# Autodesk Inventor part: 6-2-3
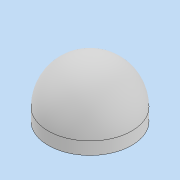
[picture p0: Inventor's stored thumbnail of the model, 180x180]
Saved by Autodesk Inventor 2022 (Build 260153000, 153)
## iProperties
Created: 2021-07
Part Number: 6-2-3
Material: 一般
Document SubType Name: Modeling
Designer: DesignLab
Density: 1 g/cm^3
Appearance: 既定
Author: DesignLab
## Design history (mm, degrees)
sketch "スケッチ1"
  geometry: L1 (0, 0)-(30, 0); L2 (0, 0)-(30, 0); L3 (0, 0)-(0, 30); L4 (30, 0)-(30, -9); L5 (30, -9)-(0, -9); L6 (0, -9)-(0, 30); A1 r 30 centre (0, 0) between (30, 0) and (0, 30); 2 further points
  constraints: 12 end point, 2 point on circle, 2 vertical, 1 centre point, 1 coincident, 1 collinear, 1 horizontal, 1 perpendicular
  dimensions: "d0" = 30 radius of A1; "d1" = 0 distance between parallel lines of L1 L2; "d2" = 90 deg angle of L1 L3; "d3" = 9 distance of L2.end L4.end
revolve "回転1" sketch "スケッチ1" stored, may be unused: angle "d4" = 90 deg
feature "シェル1" dims "d5" = 2
node "ソリッド1"
